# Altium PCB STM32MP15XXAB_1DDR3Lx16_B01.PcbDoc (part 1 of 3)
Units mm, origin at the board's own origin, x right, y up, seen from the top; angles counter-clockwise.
Board outline 86 x 120 mm, 4 copper layers (Top Layer, Signal Layer 1, Signal Layer 2, Bottom Layer), stack 1.571 mm thick; 144 components, 93 nets, 930 pads, 372 vias.
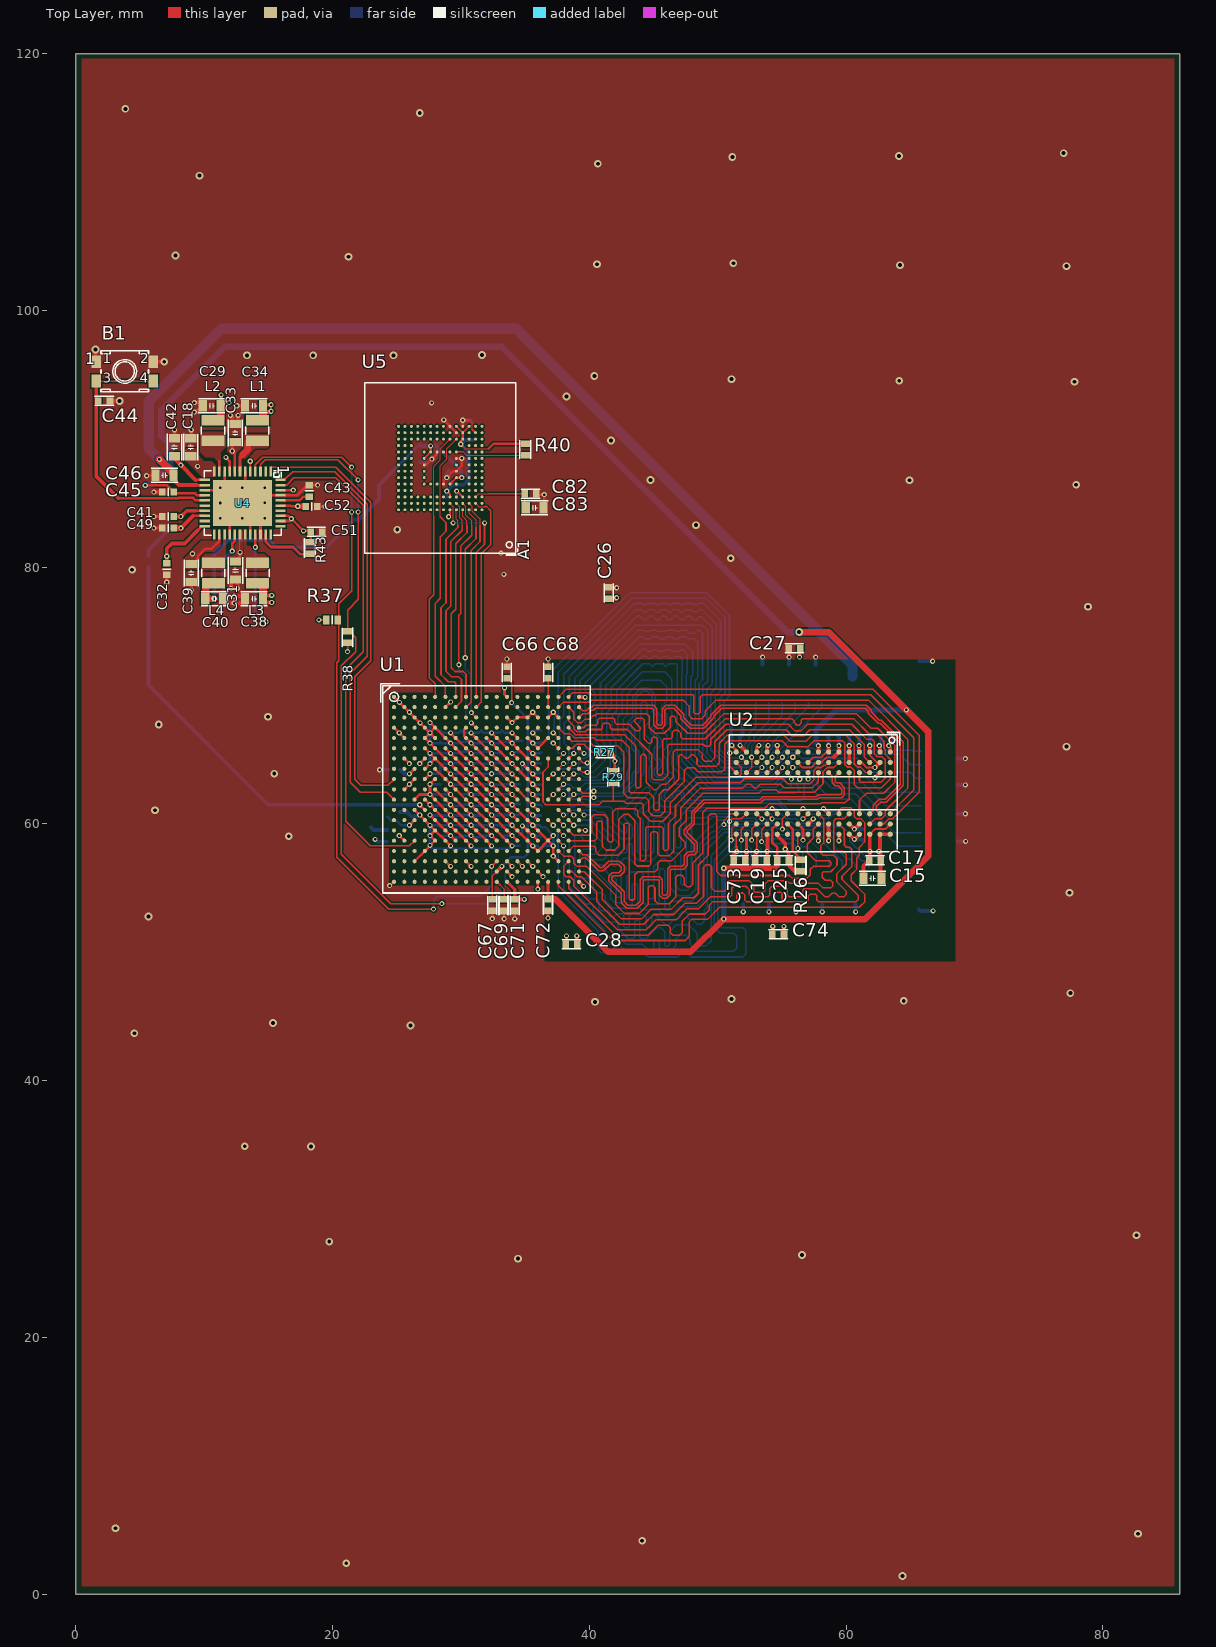
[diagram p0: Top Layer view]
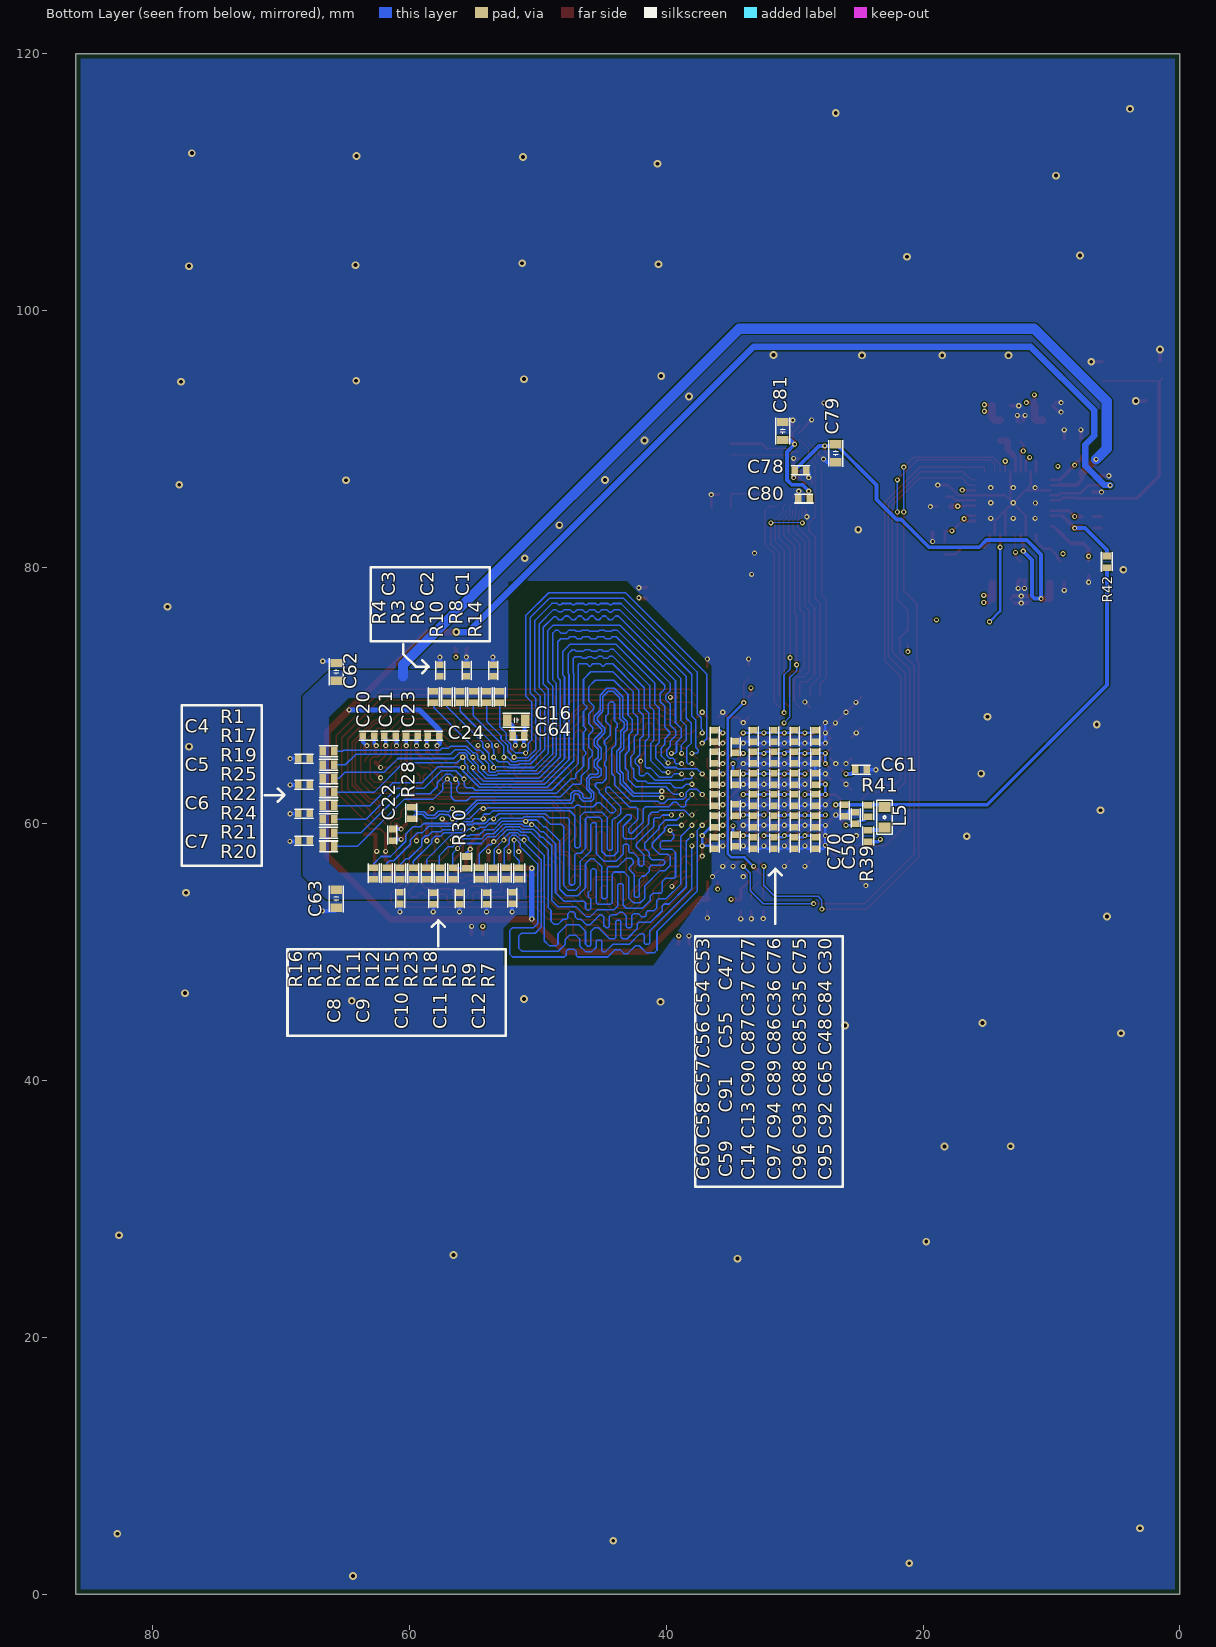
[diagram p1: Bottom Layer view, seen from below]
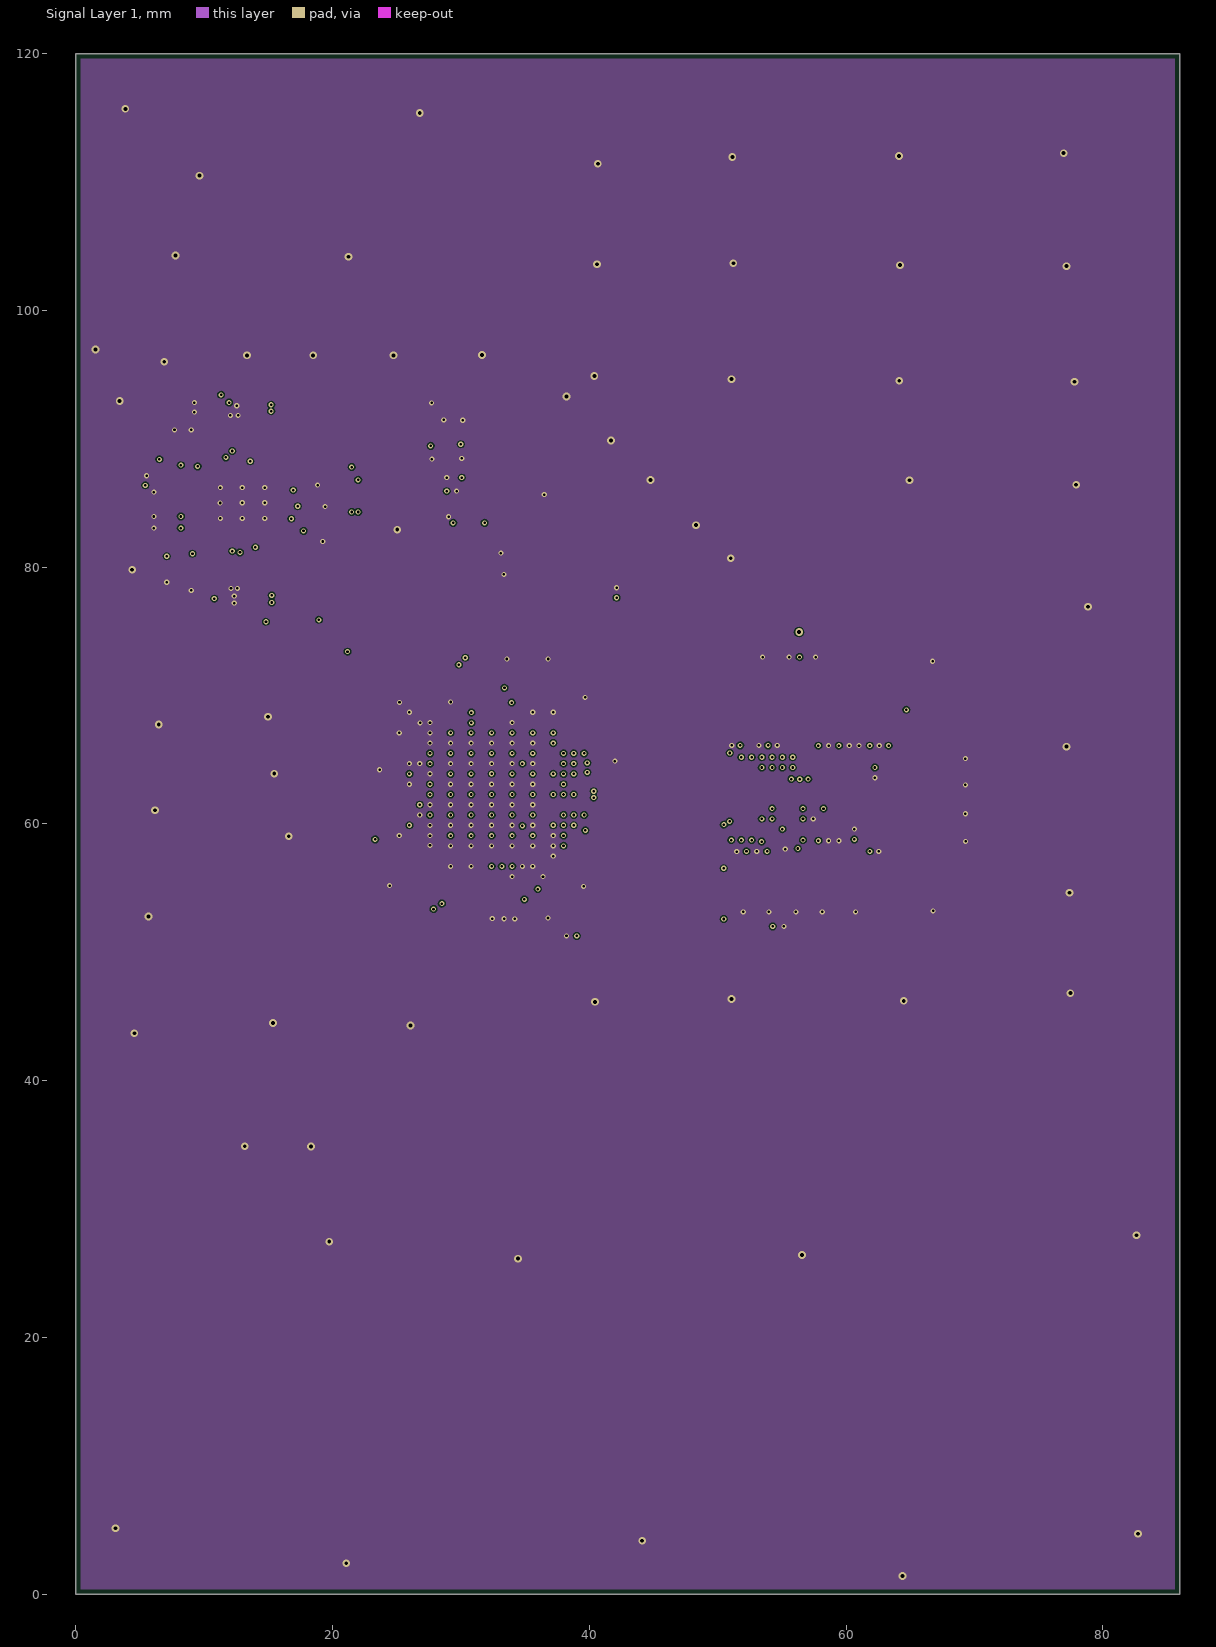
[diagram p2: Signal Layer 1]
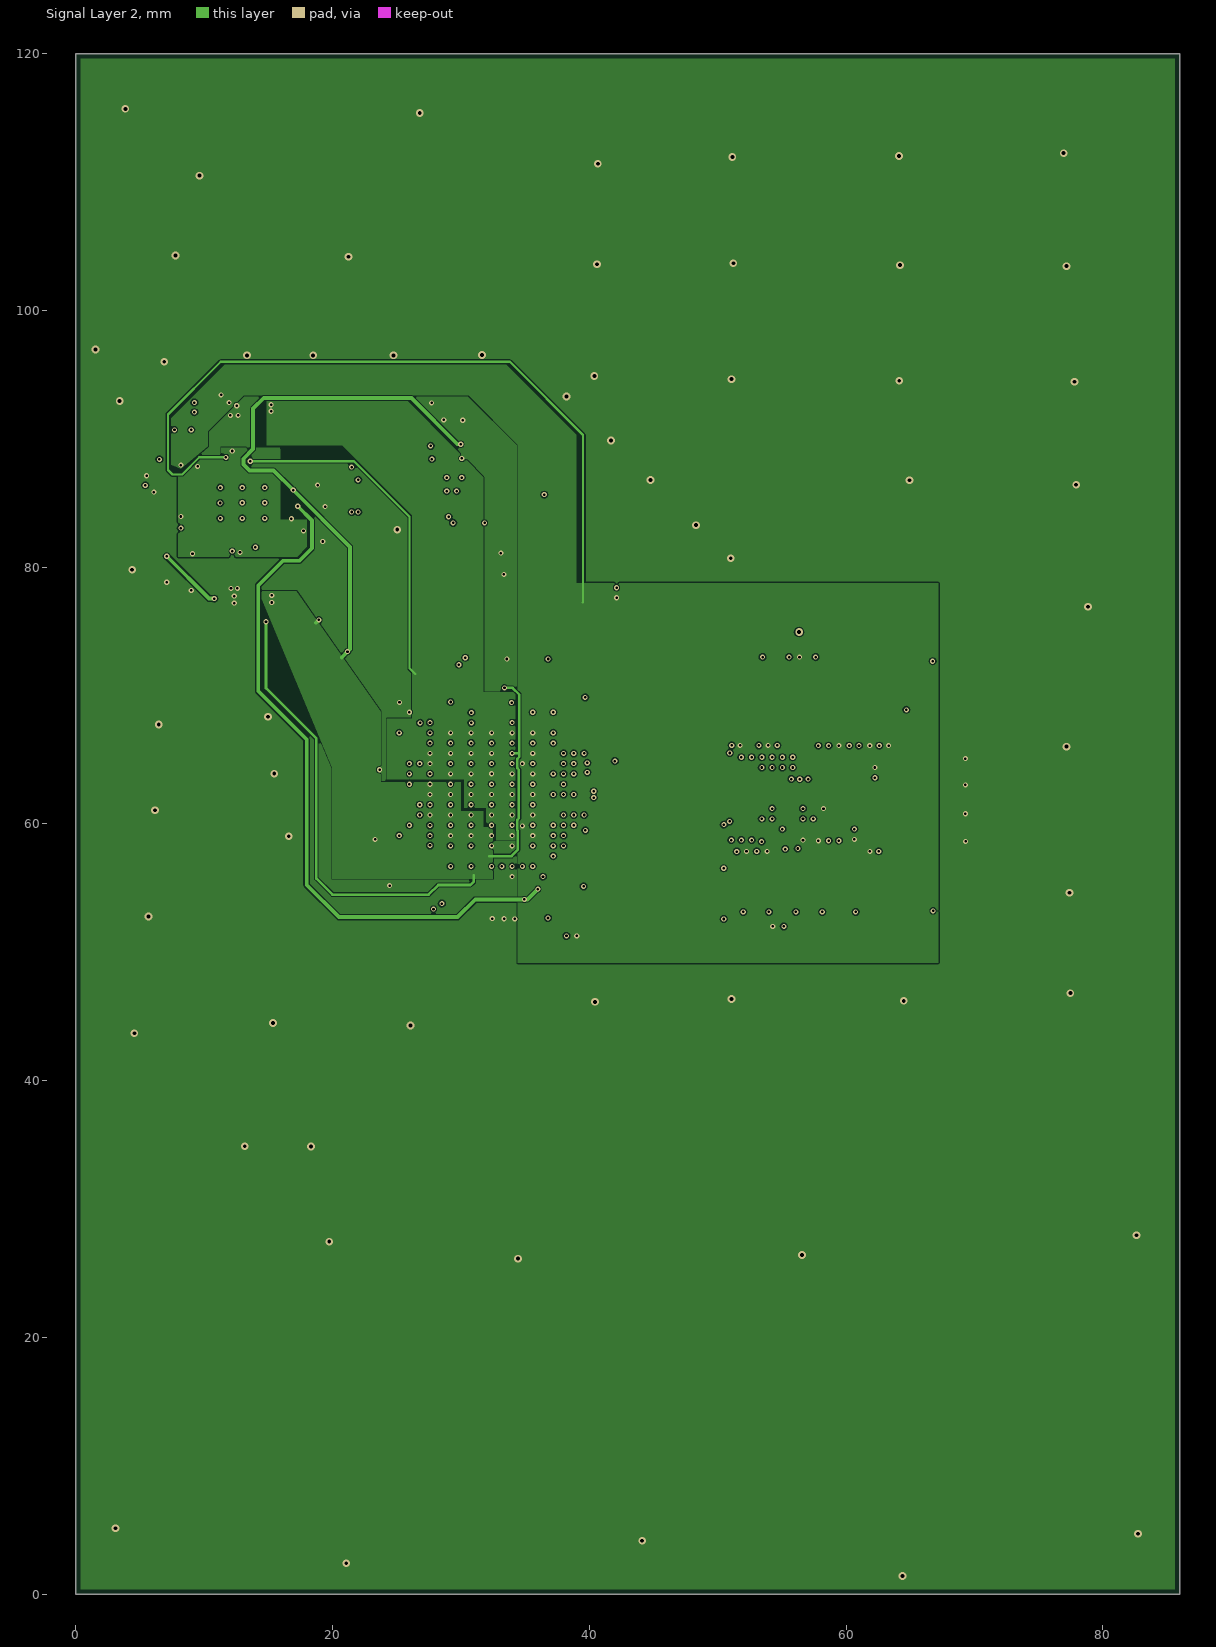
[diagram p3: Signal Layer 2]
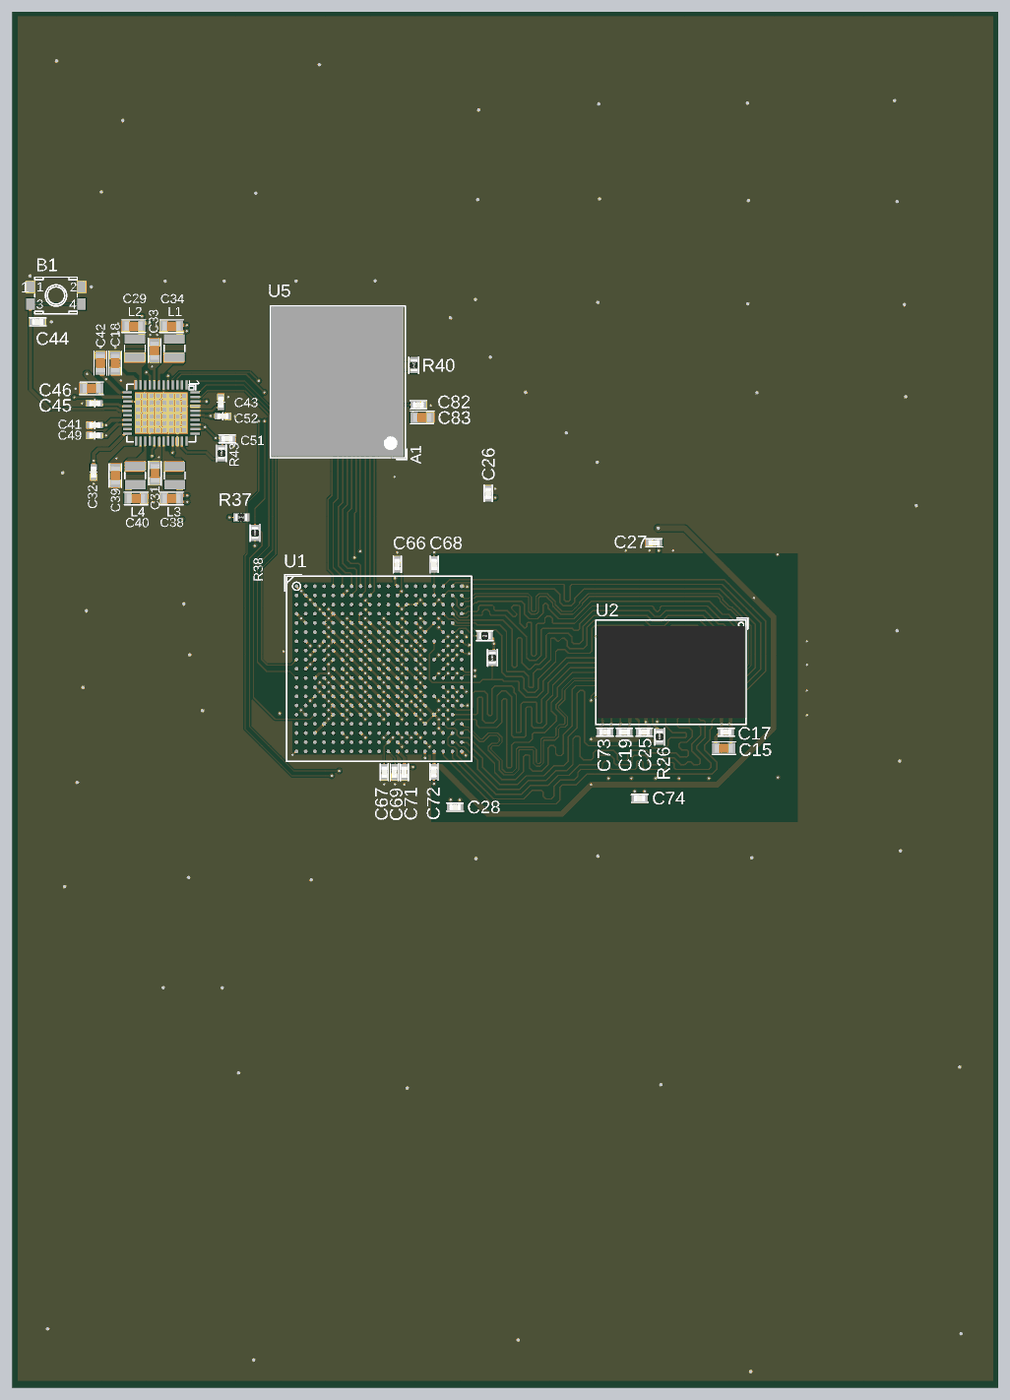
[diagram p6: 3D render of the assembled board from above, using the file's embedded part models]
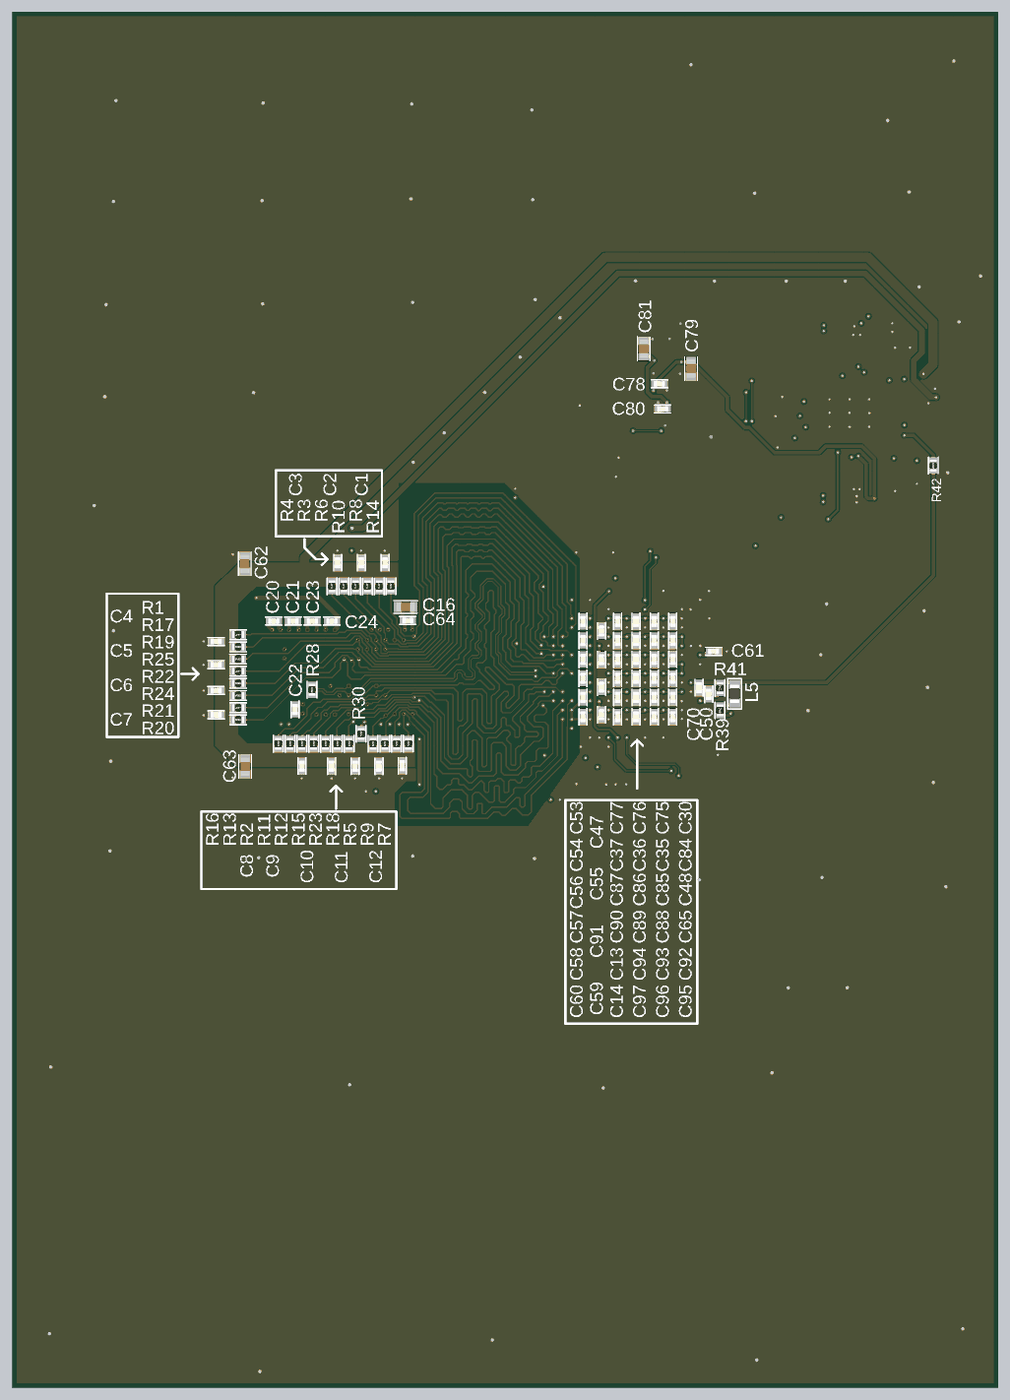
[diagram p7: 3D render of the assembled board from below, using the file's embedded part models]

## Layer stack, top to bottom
Top Solder: solder mask 0.0203, Solder Resist, Dk 3.5
Top Layer: signal copper 0.037
Dielectric 1: core 0.0986, FR-4, Dk 4.1
Signal Layer 1: signal copper 0.035
Dielectric 2: prepreg 1.23, FR-4, Dk 4.25
Signal Layer 2: signal copper 0.035
Dielectric 3: core 0.0986, FR-4, Dk 4.1
Bottom Layer: signal copper 0.037
Bottom Solder: solder mask 0.0203, Solder Resist, Dk 3.5

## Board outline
0,0 0,120 86,120 86,0

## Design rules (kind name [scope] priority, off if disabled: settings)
BoardOutlineClearance [All] p1: gap=0.4 ignorepadtopadclearanceinfootprint=FALSE
Clearance diff [InNetClass('diff')] p1: gap=0.1 ignorepadtopadclearanceinfootprint=FALSE except(0: Arc-Hole Track-Hole SMDPad-Hole THPad-Hole Via-Hole Fill-Hole Poly-Hole Region-Hole Text-Hole; 0.08: Track-SMDPad; 0.13: Track-Track; 0.15: Arc-Fill Track-Fill SMDPad-Fill THPad-Fill Via-Fill Fill-Fill; 0.2: Arc-THPad SMDPad-SMDPad SMDPad-THPad THPad-THPad)
Clearance [InNetClass('All Nets')] p2: gap=0.1 ignorepadtopadclearanceinfootprint=FALSE except(0: Arc-Hole Track-Hole SMDPad-Hole THPad-Hole Via-Hole Fill-Hole Poly-Hole Region-Hole Text-Hole; 0.09: Track-SMDPad; 0.15: Arc-Fill Track-Fill SMDPad-Fill THPad-Fill Via-Fill Fill-Fill)
ComponentClearance [All] p1 off: gap=0.025 collisioncheckmode=3 verticalgap=2540 showdistances=TRUE
DiffPairsRouting [All] p1: maxlimit=0.13 minlimit=0.13 mostfreqgap=0.13 toplayer_minwidth=0.09 toplayer_maxwidth=0.13 toplayer_prefwidth=0.1 midlayer1_minwidth=0.09 midlayer1_maxwidth=0.13 midlayer1_prefwidth=0.1 midlayer2_minwidth=0.09 midlayer2_maxwidth=0.13 midlayer2_prefwidth=0.1 bottomlayer_minwidth=0.09 bottomlayer_maxwidth=0.13 bottomlayer_prefwidth=0.1 maxuncoupledlength=0.5
FanoutControl Fanout_BGA [IsBGA] p1: bgadir=Out bgaviamode=Closest fanoutstyle=Auto fanoutdirection=Alternating viagrid=0.025 // Fanout_BGA (Default Rule)
FanoutControl Fanout_LCC [IsLCC] p2: bgadir=Out bgaviamode=Closest fanoutstyle=Auto fanoutdirection=Alternating viagrid=0.025 // Fanout_LCC (Default Rule)
FanoutControl Fanout_SOIC [IsSOIC] p3: bgadir=Out bgaviamode=Closest fanoutstyle=Auto fanoutdirection=Alternating viagrid=0.025 // Fanout_SOIC (Default Rule)
FanoutControl Fanout_Small [(CompPinCount < 5)] p4: bgadir=Out bgaviamode=Closest fanoutstyle=Auto fanoutdirection=OutThenIn viagrid=0.025 // Fanout_Small (Default Rule)
FanoutControl Fanout_Default [All] p5: bgadir=Out bgaviamode=Closest fanoutstyle=Auto fanoutdirection=Alternating viagrid=0.025 // Fanout_Default (Default Rule)
Height [All] p1 off: minheight=0 maxheight=100 prefheight=0.5
HoleSize [All] p1: absolutevalues=TRUE maxlimit=10 minlimit=0.15 maxpercent=80.000 minpercent=20.000
HoleToHoleClearance [All] p1: gap=0.25 allowstackedmicrovias=TRUE
Length Length_SDMMC1 [InNetClass('NETC_SDMMC1')] p1: maxlimit=86 minlimit=81
MinimumSolderMaskSliver [All] p1: minsoldermaskwidth=0
PlaneClearance [All] p1: clearance=0.6
PlaneConnect [All] p1: planeconnectstyle=Direct reliefexpansion=0.508 reliefentries=4 reliefconductorwidth=0.254 reliefairgap=0.254
PolygonConnect [All] p1: connectstyle=Direct reliefconductorwidth=0.254 reliefentries=4 polygonreliefangle="90 Angle" airgapwidth=0.254
RoomDefinition U_STM32_MPU_IOs [InComponentClass('U_STM32_MPU_IOs')] p1 off: confinementstyle=ConfineIn formatcopy=TRUE lockcomponents=FALSE outline 104.55,11.05 155.35,11.05 155.35,36.45 104.55,36.45
RoomDefinition U_Power_MPU [InComponentClass('U_Power_MPU')] p2 off: confinementstyle=ConfineIn formatcopy=TRUE lockcomponents=FALSE outline 87.674,18.025 101.45,18.025 101.45,24 87.674,24
RoomDefinition U_eMMC [InComponentClass('U_eMMC')] p3 off: confinementstyle=ConfineIn formatcopy=TRUE lockcomponents=FALSE outline 87.122,1.416 129.449,1.416 129.449,15.666 87.122,15.666
RoomDefinition U_1DDR3L_16bits [InComponentClass('U_1DDR3L_16bits')] p4 off: confinementstyle=ConfineIn formatcopy=TRUE lockcomponents=FALSE outline 92.5,18.4 143.3,18.4 143.3,43.8 92.5,43.8
RoomDefinition U_Power_PMIC [InComponentClass('U_Power_PMIC')] p5 off: confinementstyle=ConfineIn formatcopy=TRUE lockcomponents=FALSE outline 87.122,8.666 203.578,8.666 203.578,17.666 87.122,17.666
RoutingVias RoutingVias_GND [InNetClass('GND')] p1: holewidth=0.3 width=0.6 viastyle="Through Hole" minholewidth=0.2 minwidth=0.4 maxholewidth=0.3 maxwidth=0.6
RoutingVias RoutingVias_ALIMS [InNetClass('ALIMS')] p2: holewidth=0.3 width=0.6 viastyle="Through Hole" minholewidth=0.2 minwidth=0.4 maxholewidth=0.3 maxwidth=0.6
RoutingVias [All] p3: holewidth=0.2 width=0.4 viastyle="Through Hole" minholewidth=0.2 minwidth=0.4 maxholewidth=0.3 maxwidth=0.6
SilkToSilkClearance [All] p1: silktosilkclearance=0
SilkToSolderMaskClearance [IsPad] p1: minsilkscreentomaskgap=0 clearancetoexposedcopper=TRUE
SolderMaskExpansion [All] p1: expansion=0.05 istentingtop=FALSE
Width VDD_DDR [InNet('VDD_DDR')] p1: maxlimit=0.3 minlimit=0.1 preferedwidth=0.175
Width Width_VCORE [InNet('VDD_CORE')] p2: maxlimit=0.2 minlimit=0.175 preferedwidth=0.175
Width Width_gnd [InNet('GND')] p3: maxlimit=0.3 minlimit=0.1 preferedwidth=0.175
Width [All] p4: maxlimit=0.5 minlimit=0.09 preferedwidth=0.12 minimp=50.000000 maximp=50.000000 favimp=50.000000
15 further rules are at their usual default settings.

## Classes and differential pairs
from-to class ddr_addr_ctrl: "DDR_A0 (U1-H18 : U2-N3)" "DDR_A1 (U2-P7 : U1-M17)" "DDR_A2 (U1-G18 : U2-P3)" "DDR_A3 (U1-F19 : U2-N2)" "DDR_A4 (U2-P8 : U1-P17)" "DDR_A5 (U1-H17 : U2-P2)" "DDR_A6 (U1-N16 : U2-R8)" "DDR_A7 (U2-R2 : U1-E17)" "DDR_A8 (U1-R17 : U2-T8)" "DDR_A9 (U2-R3 : U1-G17)" "DDR_A10 (U1-M19 : U2-L7)" "DDR_A11 (U2-R7 : U1-M18)" "DDR_A12 (U1-L17 : U2-N7)" "DDR_A13 (U1-F17 : U2-T3)" "DDR_A14 (U2-T7 : U1-N18)" "DDR_A15 (U2-M7 : U1-L16)" "DDR_BA0 (U2-M2 : U1-G19)" "DDR_BA1 (U1-N17 : U2-N8)" "DDR_BA2 (U2-M3 : U1-J16)" "DDR_CASN (U1-K17 : U2-K3)" "DDR_CKE (U2-K9 : U1-P19)" "DDR_CLK_N (U2-K7 : U1-K19)" "DDR_CLK_P (U2-J7 : U1-L19)" "DDR_CSN (U1-J18 : U2-L2)" "DDR_ODT (U1-H19 : U2-K1)" "DDR_RASN (U1-L18 : U2-J3)" "DDR_WEN (U1-J17 : U2-L3)"
from-to class DDR_DQ: "DDR_DQ0 (U2-B8 : U1-A17)" "DDR_DQ1 (U2-A7 : U1-A18)" "DDR_DQ2 (U1-D18 : U2-C2)" "DDR_DQ3 (U1-B17 : U2-C8)" "DDR_DQ4 (U2-A3 : U1-E18)" "DDR_DQ5 (U1-D17 : U2-C3)" "DDR_DQ6 (U2-A2 : U1-D19)" "DDR_DQ7 (U1-B18 : U2-D7)" "DDR_DQ8 (U1-P18 : U2-G2)" "DDR_DQ9 (U2-E3 : U1-T17)" "DDR_DQ10 (U1-R18 : U2-H3)" "DDR_DQ11 (U2-H8 : U1-V19)" "DDR_DQ12 (U1-W18 : U2-F8)" "DDR_DQ13 (U2-F2 : U1-T18)" "DDR_DQ14 (U1-V18 : U2-H7)" "DDR_DQ15 (U2-F7 : U1-W17)" "DDR_DQM0 (U1-C18 : U2-D3)" "DDR_DQM1 (U2-E7 : U1-U18)" "DDR_DQS0_N (U1-B19 : U2-B7)" "DDR_DQS0_P (U2-C7 : U1-C19)" "DDR_DQS1_N (U1-T19 : U2-G3)" "DDR_DQS1_P (U2-F3 : U1-U19)"
differential pair class DIFF_CLK: DDR_CLK
differential pair class DIFF_DQS1: DDR_DQS1
differential pair class DIFF_DQS0: DDR_DQS0
polygon class POLY_DIRECT_ALL: NETC906_2_L01_P192
component class U_1DDR3L_16bits: C1 C2 C3 C4 C5 C6 C7 C8 C9 C10 C11 C12 C15 C16 C17 C19 C20 C21 C22 C23 C24 C25 C26 C27 C28 C62 C63 C64 C73 C74 R1 R2 R3 R4 R5 R6 R7 R8 R9 R10 R11 R12 R13 R14 R15 R16 R17 R18 R19 R20 R21 R22 R23 R24 R25 R26 R28 R29 R30 U2
component class U_Power_MPU: C13 C14 C30 C35 C36 C37 C47 C48 C50 C53 C54 C55 C56 C57 C58 C59 C60 C61 C65 C66 C67 C68 C69 C70 C71 C75 C76 C77 C84 C85 C86 C87 C88 C89 C90 C91 C92 C93 C94 C95 C96 C97 L5 R39 R41 R42
component class U_Power_PMIC: B1 C18 C29 C31 C32 C33 C34 C38 C39 C40 C41 C42 C43 C44 C45 C46 C49 C51 C52 L1 L2 L3 L4 R43 U4
component class U_eMMC: C78 C79 C80 C81 C82 C83 R40 U5
component class U_STM32_MPU_IOs: C72 R27 R37 R38 U1
net class eMMC_SDIO2_D[0..7]: eMMC_SDIO2_D0 eMMC_SDIO2_D1 eMMC_SDIO2_D2 eMMC_SDIO2_D3 eMMC_SDIO2_D4 eMMC_SDIO2_D5 eMMC_SDIO2_D6 eMMC_SDIO2_D7
differential pair DDR_DQS0: +DDR_DQS0_P -DDR_DQS0_N
differential pair DDR_DQS1: +DDR_DQS1_P -DDR_DQS1_N

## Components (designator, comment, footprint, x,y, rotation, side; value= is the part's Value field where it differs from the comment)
B1 "" SWI_JIUBABA_C-TS-02H-2-5-B-V-T_R_BLUE 3.825,95.25 r0 top value=SW-PUSH-TS-02H-Blue
C1 "" C0402#1 53.48,71.95 r270 bottom value=100nF
C2 "" C0402#1 55.55,71.95 r270 bottom value=100nF
C3 "" C0402#1 57.61,71.95 r270 bottom value=100nF
C4 "" C0402#1 68.21,65.08 r180 bottom value=100nF
C5 "" C0402#1 68.21,63.06 r180 bottom value=100nF
C6 "" C0402#1 68.21,60.81 r180 bottom value=100nF
C7 "" C0402#1 68.21,58.69 r180 bottom value=100nF
C8 "" C0402#1 60.73,54.22 r90 bottom value=100nF
C9 "" C0402#1 58.14,54.21 r90 bottom value=100nF
C10 "" C0402#1 56.09,54.21 r90 bottom value=100nF
C11 "" C0402#1 54.01,54.21 r90 bottom value=100nF
C12 "" C0402#1 51.99,54.25 r90 bottom value=100nF
C13 "" C0402#1 33.2,60.21 r90 bottom value=1uF
C14 "" C0402#1 33.2,58.52 r90 bottom value=1uF
C15 "" C0603#1 62.06,55.78 r180 top value=10uF
C16 "" C0603#1 51.69,68.09 r0 bottom value=10uF
C17 "" C0402#1 62.25,57.17 r180 top value=100nF
C18 "" C0603#2 8.975,89.35 r270 bottom value=10uF
C19 "" C0402#1 53.39,57.17 r0 top value=100nF
C20 "" C0402#1 63.19,66.86 r0 bottom value=100nF
C21 "" C0402#1 61.51,66.86 r0 bottom value=100nF
C22 "" C0402#1 61.33,59.16 r90 bottom value=100nF
C23 "" C0402#1 59.82,66.86 r180 bottom value=100nF
C24 "" C0402#1 58.12,66.86 r180 bottom value=100nF
C25 "" C0402#1 55.11,57.17 r180 top value=100nF
C26 "" C0402#1 41.52,78 r270 top value=100nF
C27 "" C0402#1 55.98,73.68 r0 top value=100nF
C28 "" C0402#1 38.63,50.63 r0 top value=100nF
C29 "" C0603#2 10.6,92.575 r0 bottom value=22uF
C30 "" C0402#1 28.4,66.84 r90 bottom value=1uF
C31 "" C0603#2 12.45,79.75 r90 bottom value=10uF
C32 "" C0402#2 7.1,79.85 r90 bottom value=1uF
C33 "" C0603#2 12.425,90.45 r270 bottom value=10uF
C34 "" C0603#2 13.9,92.575 r0 bottom value=22uF
C35 "" C0402#1 30,65.17 r90 bottom value=1uF
C36 "" C0402#1 31.6,65.17 r90 bottom value=1uF
C37 "" C0402#1 33.2,65.17 r90 bottom value=1uF
C38 "" C0603#2 13.9,77.55 r0 bottom value=22uF
C39 "" C0603#2 9,79.55 r90 bottom value=10uF
C40 "" C0603#2 10.8,77.55 r180 bottom value=22uF
C41 "" C0402#2 7.2,83.95 r0 bottom value=1uF
C42 "" C0603#2 7.7,89.35 r270 bottom value=10uF
C43 "" C0402#2 18.2,85.95 r270 bottom value=4.7uF
C44 "" C0402#1 2.225,92.95 r180 top value=10nF
C45 "" C0402#1 7.2,85.85 r0 top value=1uF
C46 "" C0603#1 6.925,87.15 r0 top value=10uF
C47 "" C0402#1 34.6,66 r270 bottom value=1uF
C48 "" C0402#1 28.4,63.52 r270 bottom value=1uF
C49 "" C0402#2 7.2,83.05 r0 bottom value=4.7uF
C50 "" C0402#1 25.25,60.475 r270 bottom value=1uF
C51 "" C0402#1 18.75,82.75 r0 top value=4.7uF
C52 "" C0402#1 18.375,84.725 r180 top value=4.7uF
C53 "" C0402#1 36.22,66.84 r90 bottom value=1uF
C54 "" C0402#1 36.22,65.17 r90 bottom value=1nF
C55 "" C0402#1 34.6,63.5 r90 bottom value=1uF
C56 "" C0402#1 36.22,63.52 r90 bottom value=1uF
C57 "" C0402#1 36.22,61.87 r90 bottom value=1nF
C58 "" C0402#1 36.22,60.21 r90 bottom value=1uF
C59 "" C0402#1 34.6,58.7 r90 bottom value=1uF
C60 "" C0402#1 36.22,58.52 r90 bottom value=1uF
C61 "" C0402#1 24.825,64.225 r0 bottom value=100nF
C62 "" C0603#1 65.71,71.85 r270 bottom value=22uF
C63 "" C0603#1 65.69,54.18 r90 bottom value=22uF
C64 "" C0402#1 51.5,66.91 r0 bottom value=100nF
C65 "" C0402#1 28.4,61.87 r90 bottom value=1uF
C66 "" C0402#1 33.59,71.8 r270 top value=100nF
C67 "Capacitor" C0402#1 32.45,53.69 r90 top value=2.2uF
C68 "Capacitor" C0402#1 36.8,71.8 r270 top value=2.2uF
C69 "Capacitor" C0402#1 33.325,53.675 r90 top value=2.2uF
C70 "" C0402#1 26.1,61.05 r90 bottom value=1uF
C71 "" C0402#1 34.2,53.675 r90 top value=100nF
C72 "" C0402#1 36.79,53.71 r90 top value=100nF
C73 "" C0402#1 51.7,57.17 r0 top value=100nF
C74 "" C0402#1 54.72,51.4 r180 top value=100nF
C75 "" C0402#1 30,66.84 r90 bottom value=1uF
C76 "" C0402#1 31.6,66.84 r90 bottom value=1uF
C77 "" C0402#1 33.2,66.84 r90 bottom value=1uF
C78 "" C0402#1 29.55,87.55 r0 bottom value=100nF
C79 "" C0603#1 26.8,88.875 r90 bottom value=2.2uF
C80 "" C0402#1 29.275,85.35 r180 bottom value=100nF
C81 "" C0603#1 30.925,90.6 r270 bottom value=2.2uF
C82 "" C0402#1 35.425,85.725 r180 top value=100nF
C83 "" C0603#1 35.75,84.625 r180 top value=2.2uF
C84 "" C0402#1 28.4,65.17 r90 bottom value=1uF
C85 "" C0402#1 30,63.52 r90 bottom value=1uF
C86 "" C0402#1 31.6,63.52 r90 bottom value=1uF
C87 "" C0402#1 33.2,63.52 r90 bottom value=1uF
C88 "" C0402#1 30,61.87 r90 bottom value=1uF
C89 "" C0402#1 31.6,61.87 r90 bottom value=1uF
C90 "" C0402#1 33.2,61.87 r90 bottom value=1uF
C91 "" C0402#1 34.6,61.1 r270 bottom value=1uF
C92 "" C0402#1 28.4,60.21 r90 bottom value=1uF
C93 "" C0402#1 30,60.21 r90 bottom value=1uF
C94 "" C0402#1 31.6,60.21 r90 bottom value=1uF
C95 "" C0402#1 28.4,58.52 r90 bottom value=1uF
C96 "" C0402#1 30,58.52 r90 bottom value=1uF
C97 "" C0402#1 31.6,58.52 r90 bottom value=1uF
L1 "" IND_MURATA_DFE201612P 14.15,90.65 r90 bottom value=DFE201612P-1R0M
L2 "" IND_MURATA_DFE201612P 10.7,90.65 r90 bottom value=DFE201612P-1R0M
L3 "" IND_MURATA_DFE201612P 14.175,79.55 r270 bottom value=DFE201612P-1R0M
L4 "" IND_MURATA_DFE201612P 10.725,79.55 r270 bottom value=DFE201612P-1R0M
L5 "" L0603_H0P8 23,60.525 r90 bottom value=LQM18FN4R7M00D
R1 "" R0402#1 66.3,65.67 r0 bottom value=56R
R2 "" R0402#1 60.73,56.16 r270 bottom value=56R
R3 "" R0402#1 57.08,69.9 r90 bottom value=56R
R4 "" R0402#1 58.11,69.9 r90 bottom value=56R
R5 "" R0402#1 53.5,56.16 r270 bottom value=56R
R6 "" R0402#1 56.05,69.9 r90 bottom value=56R
R7 "" R0402#1 51.45,56.16 r270 bottom value=56R
R8 "" R0402#1 53.99,69.9 r90 bottom value=56R
R9 "" R0402#1 52.48,56.16 r270 bottom value=56R
R10 "" R0402#1 55.02,69.9 r90 bottom value=56R
R11 "" R0402#1 59.7,56.16 r270 bottom value=56R
R12 "" R0402#1 58.67,56.16 r270 bottom value=56R
R13 "" R0402#1 61.76,56.16 r270 bottom value=56R
R14 "" R0402#1 52.97,69.9 r90 bottom value=56R
R15 "" R0402#1 57.64,56.16 r270 bottom value=56R
R16 "" R0402#1 62.79,56.16 r270 bottom value=56R
R17 "" R0402#1 66.3,64.61 r0 bottom value=56R
R18 "" R0402#1 54.53,56.16 r270 bottom value=56R
R19 "" R0402#1 66.3,63.55 r0 bottom value=56R
R20 "" R0402#1 66.3,58.25 r0 bottom value=56R
R21 "" R0402#1 66.3,59.31 r0 bottom value=56R
R22 "" R0402#1 66.3,61.43 r0 bottom value=56R
R23 "" R0402#1 56.61,56.16 r270 bottom value=56R
R24 "" R0402#1 66.3,60.37 r0 bottom value=56R
R25 "" R0402#1 66.3,62.49 r0 bottom value=56R
R26 "" R0402#1 56.46,56.78 r90 top value=240R
R27 "" R0402#1 41.22,65.58 r0 top value=240R
R28 "" R0402#1 59.85,60.87 r270 bottom value=100R
R29 "" R0402#1 41.875,63.65 r270 top value=10K
R30 "" R0402#1 55.57,57.02 r270 bottom value=10K
R37 "" R0402#1 19.975,75.9 r0 top value=1K5
R38 "" R0402#1 21.175,74.55 r90 top value=1K5
R39 "" R0402#1 24.275,59.075 r90 bottom value=0R
R40 "" R0402#1 35.025,89.175 r90 top value=10K
R41 "" R0402#1 24.275,61.025 r270 bottom value=0R
R42 "" R0402#1 5.675,80.425 r270 bottom value=0R
R43 "" R0402#2 18.25,81.5 r90 bottom value=47K
U1 "STM32MP157CAB3" ICC_LFBGA354_16X16_STM32MP157CAB3_P080 32,62.7 r0 top locked
U2 "" ICC_VFBGA96_9x13_P080 57.45,62.4 r270 top locked value=NT5CC256M16ER-EK
U4 "" ICC_WFQFN44-EPAD_5X6_P040 13,85 r270 top value=STPMIC1APQR
U5 "" ICC_P-WFBGA153_13X11P5_P050 28.4,87.725 r90 top locked value=THGBMDG5D1LBAIL

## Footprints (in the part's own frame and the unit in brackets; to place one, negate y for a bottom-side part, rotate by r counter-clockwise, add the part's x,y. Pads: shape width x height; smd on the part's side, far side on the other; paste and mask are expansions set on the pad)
C0402#1 [mm]
  rect 0.51x0.56 smd mask+0.05: 1(-0.45,0) 2(0.45,0)
  silkscreen extent -0.72,-0.35 0.72,0.35, body extent -0.5,-0.3 0.5,0.3, height 0.4
C0402#2 [mm]
  rect 0.51x0.56 smd far side mask+0.05: 1(-0.45,0) 2(0.45,0)
  body extent -0.5,-0.3 0.5,0.3, height 0.4
C0603#1 [mm]
  rect 0.64x0.89 smd mask+0.05: 1(-0.7,0) 2(0.7,0)
  silkscreen extent -1.05,-0.55 1.02,0.55, body extent -0.9,-0.5 0.9,0.5, height 1.4
C0603#2 [mm]
  rect 0.64x0.89 smd far side mask+0.05: 1(-0.7,0) 2(0.7,0)
  body extent -0.9,-0.5 0.9,0.5, height 1.4
ICC_LFBGA354_16X16_STM32MP157CAB3_P080 [mm] "MCD-01805"
  round 0.32 smd paste+0 mask+0.05: A1(-7.2,7.2) A2(-6.4,7.2) A3(-5.6,7.2) A4(-4.8,7.2) A5(-4,7.2) A6(-3.2,7.2) A7(-2.4,7.2) A8(-1.6,7.2) A9(-0.8,7.2) A10(0,7.2) A11(0.8,7.2) A12(1.6,7.2) A13(2.4,7.2) A14(3.2,7.2) A15(4,7.2) A16(4.8,7.2) A17(5.6,7.2) A18(6.4,7.2) A19(7.2,7.2) B1(-7.2,6.4) B2(-6.4,6.4) B3(-5.6,6.4) B4(-4.8,6.4) B5(-4,6.4) B6(-3.2,6.4) B7(-2.4,6.4) B8(-1.6,6.4) B9(-0.8,6.4) B10(0,6.4) B11(0.8,6.4) B12(1.6,6.4) B13(2.4,6.4) B14(3.2,6.4) B15(4,6.4) B16(4.8,6.4) B17(5.6,6.4) B18(6.4,6.4) B19(7.2,6.4) C1(-7.2,5.6) C2(-6.4,5.6) C3(-5.6,5.6) C4(-4.8,5.6) C5(-4,5.6) C6(-3.2,5.6) C7(-2.4,5.6) C8(-1.6,5.6) C9(-0.8,5.6) C10(0,5.6) C11(0.8,5.6) C12(1.6,5.6) C13(2.4,5.6) C14(3.2,5.6) C15(4,5.6) C16(4.8,5.6) C17(5.6,5.6) C18(6.4,5.6) C19(7.2,5.6) D1(-7.2,4.8) D2(-6.4,4.8) D3(-5.6,4.8) D4(-4.8,4.8) D5(-4,4.8) D6(-3.2,4.8) D7(-2.4,4.8) D8(-1.6,4.8) D9(-0.8,4.8) D10(0,4.8) D11(0.8,4.8) D12(1.6,4.8) D13(2.4,4.8) D14(3.2,4.8) D15(4,4.8) D16(4.8,4.8) D17(5.6,4.8) D18(6.4,4.8) D19(7.2,4.8) E1(-7.2,4) E2(-6.4,4) E3(-5.6,4) E4(-4.8,4) E5(-4,4) E6(-3.2,4) E7(-2.4,4) E8(-1.6,4) E9(-0.8,4) E10(0,4) E11(0.8,4) E12(1.6,4) E13(2.4,4) E14(3.2,4) E15(4,4) E16(4.8,4) E17(5.6,4) E18(6.4,4) F1(-7.2,3.2) F2(-6.4,3.2) F3(-5.6,3.2) F4(-4.8,3.2) F5(-4,3.2) F6(-3.2,3.2) F7(-2.4,3.2) F8(-1.6,3.2) F9(-0.8,3.2) F10(0,3.2) F11(0.8,3.2) F12(1.6,3.2) F13(2.4,3.2) F14(3.2,3.2) F15(4,3.2) F17(5.6,3.2) F18(6.4,3.2) F19(7.2,3.2) G1(-7.2,2.4) G2(-6.4,2.4) G3(-5.6,2.4) G4(-4.8,2.4) G5(-4,2.4) G6(-3.2,2.4) G7(-2.4,2.4) G8(-1.6,2.4) G9(-0.8,2.4) G10(0,2.4) G11(0.8,2.4) G12(1.6,2.4) G13(2.4,2.4) G14(3.2,2.4) G15(4,2.4) G16(4.8,2.4) G17(5.6,2.4) G18(6.4,2.4) G19(7.2,2.4) H1(-7.2,1.6) H2(-6.4,1.6) H3(-5.6,1.6) H4(-4.8,1.6) H5(-4,1.6) H6(-3.2,1.6) H7(-2.4,1.6) H8(-1.6,1.6) H9(-0.8,1.6) H10(0,1.6) H11(0.8,1.6) H12(1.6,1.6) H13(2.4,1.6) H14(3.2,1.6) H15(4,1.6) H17(5.6,1.6) H18(6.4,1.6) H19(7.2,1.6) J1(-7.2,0.8) J2(-6.4,0.8) J3(-5.6,0.8) J4(-4.8,0.8) J5(-4,0.8) J6(-3.2,0.8) J7(-2.4,0.8) J8(-1.6,0.8) J9(-0.8,0.8) J10(0,0.8) J11(0.8,0.8) J12(1.6,0.8) J13(2.4,0.8) J14(3.2,0.8) J15(4,0.8) J16(4.8,0.8) J17(5.6,0.8) J18(6.4,0.8) J19(7.2,0.8) K1(-7.2,0) K2(-6.4,0) K3(-5.6,0) K4(-4.8,0) K5(-4,0) K6(-3.2,0) K7(-2.4,0) K8(-1.6,0) K9(-0.8,0) K10(0,0) K11(0.8,0) K12(1.6,0) K13(2.4,0) K14(3.2,0) K15(4,0) K17(5.6,0) K18(6.4,0) K19(7.2,0) L1(-7.2,-0.8) L2(-6.4,-0.8) L3(-5.6,-0.8) L4(-4.8,-0.8) L5(-4,-0.8) L6(-3.2,-0.8) L7(-2.4,-0.8) L8(-1.6,-0.8) L9(-0.8,-0.8) L10(0,-0.8) L11(0.8,-0.8) L12(1.6,-0.8) L13(2.4,-0.8) L14(3.2,-0.8) L15(4,-0.8) L16(4.8,-0.8) L17(5.6,-0.8) L18(6.4,-0.8) L19(7.2,-0.8) M1(-7.2,-1.6) M2(-6.4,-1.6) M3(-5.6,-1.6) M4(-4.8,-1.6) M5(-4,-1.6) M6(-3.2,-1.6) M7(-2.4,-1.6) M8(-1.6,-1.6) M9(-0.8,-1.6) M10(0,-1.6) M11(0.8,-1.6) M12(1.6,-1.6) M13(2.4,-1.6) M14(3.2,-1.6) M15(4,-1.6) M17(5.6,-1.6) M18(6.4,-1.6) M19(7.2,-1.6) N1(-7.2,-2.4) N2(-6.4,-2.4) N3(-5.6,-2.4) N4(-4.8,-2.4) N5(-4,-2.4) N6(-3.2,-2.4) N7(-2.4,-2.4) N8(-1.6,-2.4) N9(-0.8,-2.4) N10(0,-2.4) N11(0.8,-2.4) N12(1.6,-2.4) N13(2.4,-2.4) N14(3.2,-2.4) N15(4,-2.4) N16(4.8,-2.4) N17(5.6,-2.4) N18(6.4,-2.4) N19(7.2,-2.4) P1(-7.2,-3.2) P2(-6.4,-3.2) P3(-5.6,-3.2) P4(-4.8,-3.2) P5(-4,-3.2) P6(-3.2,-3.2) P7(-2.4,-3.2) P8(-1.6,-3.2) P9(-0.8,-3.2) P10(0,-3.2) P11(0.8,-3.2) P12(1.6,-3.2) P13(2.4,-3.2) P14(3.2,-3.2) P15(4,-3.2) P17(5.6,-3.2) P18(6.4,-3.2) P19(7.2,-3.2) R1(-7.2,-4) R2(-6.4,-4) R3(-5.6,-4) R4(-4.8,-4) R5(-4,-4) R6(-3.2,-4) R7(-2.4,-4) R8(-1.6,-4) R9(-0.8,-4) R10(0,-4) R11(0.8,-4) R12(1.6,-4) R13(2.4,-4) R14(3.2,-4) R15(4,-4) R16(4.8,-4) R17(5.6,-4) R18(6.4,-4) T1(-7.2,-4.8) T2(-6.4,-4.8) T3(-5.6,-4.8) T4(-4.8,-4.8) T5(-4,-4.8) T6(-3.2,-4.8) T7(-2.4,-4.8) T8(-1.6,-4.8) T9(-0.8,-4.8) T10(0,-4.8) T11(0.8,-4.8) T12(1.6,-4.8) T13(2.4,-4.8) T14(3.2,-4.8) T15(4,-4.8) T16(4.8,-4.8) T17(5.6,-4.8) T18(6.4,-4.8) T19(7.2,-4.8) U1(-7.2,-5.6) U2(-6.4,-5.6) U3(-5.6,-5.6) U4(-4.8,-5.6) U5(-4,-5.6) U6(-3.2,-5.6) U7(-2.4,-5.6) U8(-1.6,-5.6) U9(-0.8,-5.6) U10(0,-5.6) U11(0.8,-5.6) U12(1.6,-5.6) U13(2.4,-5.6) U14(3.2,-5.6) U15(4,-5.6) U16(4.8,-5.6) U17(5.6,-5.6) U18(6.4,-5.6) U19(7.2,-5.6) V1(-7.2,-6.4) V2(-6.4,-6.4) V3(-5.6,-6.4) V4(-4.8,-6.4) V5(-4,-6.4) V6(-3.2,-6.4) V7(-2.4,-6.4) V8(-1.6,-6.4) V9(-0.8,-6.4) V10(0,-6.4) V11(0.8,-6.4) V12(1.6,-6.4) V13(2.4,-6.4) V14(3.2,-6.4) V15(4,-6.4) V16(4.8,-6.4) V17(5.6,-6.4) V18(6.4,-6.4) V19(7.2,-6.4) W1(-7.2,-7.2) W2(-6.4,-7.2) W3(-5.6,-7.2) W4(-4.8,-7.2) W5(-4,-7.2) W6(-3.2,-7.2) W7(-2.4,-7.2) W8(-1.6,-7.2) W9(-0.8,-7.2) W10(0,-7.2) W11(0.8,-7.2) W12(1.6,-7.2) W13(2.4,-7.2) W14(3.2,-7.2) W15(4,-7.2) W16(4.8,-7.2) W17(5.6,-7.2) W18(6.4,-7.2) W19(7.2,-7.2)
  silkscreen extent -8.23,-8.08 8.08,8.23, body extent -8.08,-8.08 8.08,8.08, height 1.3
ICC_P-WFBGA153_13X11P5_P050 [mm]
  round 0.23 smd mask+0.05: A1(-3.25,-3.25) A2(-3.25,-2.75) A3(-3.25,-2.25) A4(-3.25,-1.75) A5(-3.25,-1.25) A6(-3.25,-0.75) A7(-3.25,-0.25) A8(-3.25,0.25) A9(-3.25,0.75) A10(-3.25,1.25) A11(-3.25,1.75) A12(-3.25,2.25) A13(-3.25,2.75) A14(-3.25,3.25) B1(-2.75,-3.25) B2(-2.75,-2.75) B3(-2.75,-2.25) B4(-2.75,-1.75) B5(-2.75,-1.25) B6(-2.75,-0.75) B7(-2.75,-0.25) B8(-2.75,0.25) B9(-2.75,0.75) B10(-2.75,1.25) B11(-2.75,1.75) B12(-2.75,2.25) B13(-2.75,2.75) B14(-2.75,3.25) C1(-2.25,-3.25) C2(-2.25,-2.75) C3(-2.25,-2.25) C4(-2.25,-1.75) C5(-2.25,-1.25) C6(-2.25,-0.75) C7(-2.25,-0.25) C8(-2.25,0.25) C9(-2.25,0.75) C10(-2.25,1.25) C11(-2.25,1.75) C12(-2.25,2.25) C13(-2.25,2.75) C14(-2.25,3.25) D1(-1.75,-3.25) D2(-1.75,-2.75) D3(-1.75,-2.25) D4(-1.75,-1.75) D12(-1.75,2.25) D13(-1.75,2.75) D14(-1.75,3.25) E1(-1.25,-3.25) E2(-1.25,-2.75) E3(-1.25,-2.25) E5(-1.25,-1.25) E6(-1.25,-0.75) E7(-1.25,-0.25) E8(-1.25,0.25) E9(-1.25,0.75) E10(-1.25,1.25) E12(-1.25,2.25) E13(-1.25,2.75) E14(-1.25,3.25) F1(-0.75,-3.25) F2(-0.75,-2.75) F3(-0.75,-2.25) F5(-0.75,-1.25) F10(-0.75,1.25) F12(-0.75,2.25) F13(-0.75,2.75) F14(-0.75,3.25) G1(-0.25,-3.25) G2(-0.25,-2.75) G3(-0.25,-2.25) G5(-0.25,-1.25) G10(-0.25,1.25) G12(-0.25,2.25) G13(-0.25,2.75) G14(-0.25,3.25) H1(0.25,-3.25) H2(0.25,-2.75) H3(0.25,-2.25) H5(0.25,-1.25) H10(0.25,1.25) H12(0.25,2.25) H13(0.25,2.75) H14(0.25,3.25) J1(0.75,-3.25) J2(0.75,-2.75) J3(0.75,-2.25) J5(0.75,-1.25) J10(0.75,1.25) J12(0.75,2.25) J13(0.75,2.75) J14(0.75,3.25) K1(1.25,-3.25) K2(1.25,-2.75) K3(1.25,-2.25) K5(1.25,-1.25) K6(1.25,-0.75) K7(1.25,-0.25) K8(1.25,0.25) K9(1.25,0.75) K10(1.25,1.25) K12(1.25,2.25) K13(1.25,2.75) K14(1.25,3.25) L1(1.75,-3.25) L2(1.75,-2.75) L3(1.75,-2.25) L12(1.75,2.25) L13(1.75,2.75) L14(1.75,3.25) M1(2.25,-3.25) M2(2.25,-2.75) M3(2.25,-2.25) M4(2.25,-1.75) M5(2.25,-1.25) M6(2.25,-0.75) M7(2.25,-0.25) M8(2.25,0.25) M9(2.25,0.75) M10(2.25,1.25) M11(2.25,1.75) M12(2.25,2.25) M13(2.25,2.75) M14(2.25,3.25) N1(2.75,-3.25) N2(2.75,-2.75) N3(2.75,-2.25) N4(2.75,-1.75) N5(2.75,-1.25) N6(2.75,-0.75) N7(2.75,-0.25) N8(2.75,0.25) N9(2.75,0.75) N10(2.75,1.25) N11(2.75,1.75) N12(2.75,2.25) N13(2.75,2.75) N14(2.75,3.25) P1(3.25,-3.25) P2(3.25,-2.75) P3(3.25,-2.25) P4(3.25,-1.75) P5(3.25,-1.25) P6(3.25,-0.75) P7(3.25,-0.25) P8(3.25,0.25) P9(3.25,0.75) P10(3.25,1.25) P11(3.25,1.75) P12(3.25,2.25) P13(3.25,2.75) P14(3.25,3.25)
  silkscreen extent -6.78,-6.02 6.63,5.87, body extent -6.55,-5.8 6.55,5.8, height 1
ICC_VFBGA96_9x13_P080 [mm]
  round 0.4 smd mask+0.05: A1(-3.2,6) A2(-2.4,6) A3(-1.6,6) A7(1.6,6) A8(2.4,6) A9(3.2,6) B1(-3.2,5.2) B2(-2.4,5.2) B3(-1.6,5.2) B7(1.6,5.2) B8(2.4,5.2) B9(3.2,5.2) C1(-3.2,4.4) C2(-2.4,4.4) C3(-1.6,4.4) C7(1.6,4.4) C8(2.4,4.4) C9(3.2,4.4) D1(-3.2,3.6) D2(-2.4,3.6) D3(-1.6,3.6) D7(1.6,3.6) D8(2.4,3.6) D9(3.2,3.6) E1(-3.2,2.8) E2(-2.4,2.8) E3(-1.6,2.8) E7(1.6,2.8) E8(2.4,2.8) E9(3.2,2.8) F1(-3.2,2) F2(-2.4,2) F3(-1.6,2) F7(1.6,2) F8(2.4,2) F9(3.2,2) G1(-3.2,1.2) G2(-2.4,1.2) G3(-1.6,1.2) G7(1.6,1.2) G8(2.4,1.2) G9(3.2,1.2) H1(-3.2,0.4) H2(-2.4,0.4) H3(-1.6,0.4) H7(1.6,0.4) H8(2.4,0.4) H9(3.2,0.4) J1(-3.2,-0.4) J2(-2.4,-0.4) J3(-1.6,-0.4) J7(1.6,-0.4) J8(2.4,-0.4) J9(3.2,-0.4) K1(-3.2,-1.2) K2(-2.4,-1.2) K3(-1.6,-1.2) K7(1.6,-1.2) K8(2.4,-1.2) K9(3.2,-1.2) L1(-3.2,-2) L2(-2.4,-2) L3(-1.6,-2) L7(1.6,-2) L8(2.4,-2) L9(3.2,-2) M1(-3.2,-2.8) M2(-2.4,-2.8) M3(-1.6,-2.8) M7(1.6,-2.8) M8(2.4,-2.8) M9(3.2,-2.8) N1(-3.2,-3.6) N2(-2.4,-3.6) N3(-1.6,-3.6) N7(1.6,-3.6) N8(2.4,-3.6) N9(3.2,-3.6) P1(-3.2,-4.4) P2(-2.4,-4.4) P3(-1.6,-4.4) P7(1.6,-4.4) P8(2.4,-4.4) P9(3.2,-4.4) R1(-3.2,-5.2) R2(-2.4,-5.2) R3(-1.6,-5.2) R7(1.6,-5.2) R8(2.4,-5.2) R9(3.2,-5.2) T1(-3.2,-6) T2(-2.4,-6) T3(-1.6,-6) T7(1.6,-6) T8(2.4,-6) T9(3.2,-6)
  silkscreen extent -4.72,-6.55 4.55,6.73, body extent -4.55,-6.55 4.55,6.55, height 1
ICC_WFQFN44-EPAD_5X6_P040 [mm]
  rect 0.8x0.2 smd mask+0.05: 1(-2.45,2.2) 2(-2.45,1.8) 3(-2.45,1.4) 4(-2.45,1) 5(-2.45,0.6) 6(-2.45,0.2) 7(-2.45,-0.2) 8(-2.45,-0.6) 9(-2.45,-1) 10(-2.45,-1.4) 11(-2.45,-1.8) 12(-2.45,-2.2) 23(2.45,-2.2) 24(2.45,-1.8) 25(2.45,-1.4) 26(2.45,-1) 27(2.45,-0.6) 28(2.45,-0.2) 29(2.45,0.2) 30(2.45,0.6) 31(2.45,1) 32(2.45,1.4) 33(2.45,1.8) 34(2.45,2.2)
  rect 0.2x0.8 smd mask+0.05: 13(-1.8,-2.95) 14(-1.4,-2.95) 15(-1,-2.95) 16(-0.6,-2.95) 17(-0.2,-2.95) 18(0.2,-2.95) 19(0.6,-2.95) 20(1,-2.95) 21(1.4,-2.95) 22(1.8,-2.95) 35(1.8,2.95) 36(1.4,2.95) 37(1,2.95) 38(0.6,2.95) 39(0.2,2.95) 40(-0.2,2.95) 41(-0.6,2.95) 42(-1,2.95) 43(-1.4,2.95) 44(-1.8,2.95)
  rect 3.6x4.6 smd paste-1.8 mask+0.05: ep(0,0)
  silkscreen extent -2.5,-3 2.5,3, body extent -2.5,-3 2.5,3, height 0.81
IND_MURATA_DFE201612P [mm] "MCD-01491"
  rect 0.8x1.8 smd far side mask+0.05: 1(-0.8,0) 2(0.8,0)
  body extent -1.1,-0.9 1.1,0.9, height 1.2
L0603_H0P8 [mm]
  rect 0.8x0.95 smd mask+0.05: 1(-0.8,0) 2(0.8,0)
  silkscreen extent -1.33,-0.6 1.33,0.6, body extent -0.87,-0.47 0.87,0.47, height 0.9
R0402#1 [mm]
  rect 0.51x0.7 smd mask+0.05: 1(-0.45,0) 2(0.45,0)
  silkscreen extent -0.72,-0.43 0.72,0.43, body extent -0.52,-0.3 0.52,0.3, height 0.4
R0402#2 [mm]
  rect 0.51x0.7 smd far side mask+0.05: 1(-0.45,0) 2(0.45,0)
  body extent -0.52,-0.3 0.52,0.3, height 0.4
SWI_JIUBABA_C-TS-02H-2-5-B-V-T_R_BLUE [mm] "BLUE"
  rect 0.75x1 smd mask+0.05: 1(-2.225,0.75) 2(2.225,0.75) 3(-2.225,-0.75) 4(2.225,-0.75)
  silkscreen extent -1.85,-1.6 1.85,1.6, body extent -2.45,-1.6 2.45,1.6, height 2.6

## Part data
B1: library part MCD-00172, "Switch HW SMD blue", Manufacturer=JIUBABA, Manufacturer_Part_Number="C-TS-02H-2.5-B-V-T/R BLUE"
C1 C2 C3 C4 C5 C6 C7 C8 C9 C10 C11 C12 C17 C19 C20 C21 C22 C23 C24 C25 C26 C27 C28 C61 C64 C66 C71 C72 C73 C74 C78 C80 C82: library part MCD-00006, "Capacitor, MLCC, 100nF, 16V, X7R, 10%, 0402, T=0.5mm", Alternate_Manufacturer=MURATA, Alternate_Manufacturer_Part_Number=GCM155R71C104KA55D, Manufacturer=YAGEO, Manufacturer_Part_Number=CC0402KRX7R7BB104, Package=C0402
C13 C14 C30 C32 C35 C36 C37 C41 C45 C47 C48 C50 C53 C55 C56 C58 C59 C60 C65 C70 C75 C76 C77 C84 C85 C86 C87 C88 C89 C90 C91 C92 C93 C94 C95 C96 C97: library part MCD-00095, "Capacitor, MLCC, 1uF, 6V3, X5R, 10%, 0402, T=0,5mm", Alternate_Manufacturer=MURATA, Alternate_Manufacturer_Part_Number=GRM155R60J105KE19, Manufacturer_Part_Number=GRM155R61E105KA12, Package=C0402
C15 C16 C18 C31 C33 C39 C42 C46: library part MCD-00099, "Capacitor, MLCC, 10uF, 10V, X5R, 10%, 0603, T=0,8mm", Manufacturer=MURATA, Manufacturer_Part_Number=GRM188R61A106KE69D, Package=C0603
C29 C34 C38 C40 C62 C63: library part MCD-00100, "Capacitor, MLCC, 22uF, 6V3, X5R, 20%, 0603, T=0,8mm", Manufacturer=MURATA, Manufacturer_Part_Number=GRM188R60J226MEA0J, Package=C0603
C43 C49 C51 C52: library part MCD-01356, "Capacitor, MLCC, 4.7uF, 6V3, X5R, 20%, 0402, T=0,5mm", Manufacturer=MURATA, Manufacturer_Part_Number=GRM155R60J475ME47, Package=C0402
C44: library part MCD-00011, "Capacitor, MLCC, 10nF, 16V, X7R, 10%, 0402, T=0.5mm", Manufacturer=YAGEO, Manufacturer_Part_Number=CC0402KRX7R7BB103, Package=C0402
C54 C57: library part MCD-00198, "Capacitor, MLCC, 1nF, 16V, X7R, 10%, 0402, T=0.5mm", Manufacturer=YAGEO, Manufacturer_Part_Number=CC0402KRX7R7BB102, Package=C0402
C67 C68 C69: library part MCD-01823, "Capacitor,MLCC,2.2uF,6V3,X5R,10%,0402,T=0.5", Manufacturer=MURATA, Manufacturer_Part_Number=GRM155R60J225KE95D, Package=C0402
C79 C81 C83: library part MCD-00012, "Capacitor, MLCC, 2.2uF, 10V, X5R, 10%, 0603, T=0,8mm", Alternate_Manufacturer=KEMET, Alternate_Manufacturer_Part_Number=C0603C225K8PACTU, Manufacturer=YAGEO, Manufacturer_Part_Number=CC0603KRX5R6BB225, Package=C0603
L1 L2 L3 L4: library part MCD-01491, "Inductors 1.0uH 54mOhms3.3A +/-20% 2016", Manufacturer=MURATA, Manufacturer_Part_Number=DFE201612P-1R0M, Package=2016
L5: library part MCD-01134, "IND 4.7uH 20% 80mA 600mhom 0603", Manufacturer=MURATA, Manufacturer_Part_Number=LQM18FN4R7M00D, Package=0603
R1 R2 R3 R4 R5 R6 R7 R8 R9 R10 R11 R12 R13 R14 R15 R16 R17 R18 R19 R20 R21 R22 R23 R24 R25: library part MCD-00118, "Resistor,56R,0402,1%,1/16W", Manufacturer=YAGEO, Manufacturer_Part_Number=RC0402FR-0756RL, Package=R0402
R26 R27: library part MCD-00120, "Resistor,240R,0402,1%,1/16W", Manufacturer=YAGEO, Manufacturer_Part_Number=RC0402FR-07240RL, Package=R0402
R28: library part MCD-00119, "Resistor,100R,0402,1%,1/16W", Manufacturer=YAGEO, Manufacturer_Part_Number=RC0402FR-07100RL, Package=R0402
R29 R30 R40: library part MCD-00053, "Resistor,10K,0402,1%,1/16W", Manufacturer=YAGEO, Manufacturer_Part_Number=RC0402FR-0710KL, Package=R0402
R37 R38: library part MCD-00068, "Resistor,1K5,0402,1%,1/16W", Manufacturer=YAGEO, Manufacturer_Part_Number=RC0402FR-071K5L, Package=R0402
R39 R41 R42: library part MCD-00052, "Resistor,0R,0402,5%,1/16W", Manufacturer=YAGEO, Manufacturer_Part_Number=RC0402JR-070RL, Package=R0402
R43: library part MCD-00063, "Resistor,47K,0402,1%,1/16W", Manufacturer=YAGEO, Manufacturer_Part_Number=RC0402FR-0747KL, Package=R0402
U1: library part MCD-01805, "MPU LFBGA 16x16x1.271 PITCH 0.8 mm secure boot + crypto", Manufacturer=STMICROELECTRONICS, Package=LFBGA
U2: library part MCD-01811, "Memory,DDR3L,4Gb,256Mbx16,933Mhz,1V35,TFBGA", Manufacturer=NANYA, Manufacturer_Part_Number=NT5CC256M16ER-EK
U4: library part MCD-01650, "ST PMIC:  4 step-down + 1 advanced boost SMPS, 6 LDOs, 2 pwr switches, DDR Vref, NVM option 'A' for IO@3.3V", Manufacturer=STMICROELECTRONICS, Manufacturer_Part_Number=STPMIC1APQR, Package="WFQFN 5.0x6.0x0.80mm"
U5: library part MCD-00110, "Memory,e-MMC,4GB,3V3,WFBGA,153pins", Manufacturer=TOSHIBA, Manufacturer_Part_Number=THGBMDG5D1LBAIL

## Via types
v1: diameter 0.4, hole 0.2, Top Layer to Bottom Layer, tented both sides, 309 vias
v2: diameter 0.6, hole 0.3, Top Layer to Bottom Layer, tented both sides, 61 vias
v3: diameter 0.4, hole 0.2, Top Layer to Signal Layer 1, tented top, 2 vias

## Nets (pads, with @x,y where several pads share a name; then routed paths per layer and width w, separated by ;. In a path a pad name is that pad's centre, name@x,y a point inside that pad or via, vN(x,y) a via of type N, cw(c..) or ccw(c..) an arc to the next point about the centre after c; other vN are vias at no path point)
3V3: C32.2 C40.2 C78.2 C79.2 L4.2 U4.22 U4.27 U5.E6 U5.F5 U5.J10 U5.K9 | length 48.6
  Top Layer w0.175: U5.J10@27.15,88.475 U5.K9@27.65,88.975 v1(27.65,89.45) ; U5.E6@29.15,86.475 U5.F5@29.65,86.975 v1(30.075,86.975)
  Top Layer w0.2: 9.5,82.85 9.85,83.2 U4.22@10.05,83.2 ; v1(12.2,81.25) 12.2,81.85 12.4,82.05 U4.27@12.4,82.55
  Top Layer w0.3: C32.2@7.1,80.5 v1(7.1,80.85) 7.1,81.45 7.5,81.85 8.5,81.85 9.5,82.85
  Top Layer w0.5: C40.2@10.125,77.55 v1(10.8,77.55)
  Top Layer w0.6: C40.2@10.125,77.55 L4.2@10.125,78.75
  Signal Layer 2 w0.3: v1(7.1,80.85) 10.4,77.55 v1(10.8,77.55)
  Bottom Layer w0.1: C79.2@26.8,89.575 C79.2@26.925,89.45 ; v1@30,87.05 v1(30.075,86.975)
  Bottom Layer w0.3: v1(12.2,81.25) 11.525,80.575 11.525,77.75 11.325,77.55 v1(10.8,77.55) 10.8,81 11.925,82.125 15.05,82.125 15.625,81.55 19.525,81.55 21.7,83.725 22.075,83.725 23.625,85.275 23.625,86.4 C79.2@26.8,89.575 ; C79.2@26.925,89.45 v1(27.65,89.45) 28.1,89.45 C78.2@30,87.55 v1@30,87.05
5V_VIN: C18.2 C31.2 C33.2 C39.2 C41.2 C51.1 R43.2 U4.8 U4.12 U4.19 U4.24 U4.28 U4.36 U4.37 | length 15.1
  Top Layer w0.09: v1(12.8,81.15) U4.28@12.8,82.55
  Top Layer w0.12: R43.2@18.25,81.95 R43.2@18.3,82
  Top Layer w0.2: C39.2@9.3,80.45 9.525,80.675 9.525,80.875 10.1,81.45 10.6,81.45 11.2,82.05 U4.24@11.2,82.55 ; 9.35,84.4 U4.19@10.05,84.4 ; C31.2@12.4,80.45 12.8,80.85 v1(12.8,81.15) ; U4.8@12.4,87.45 12.4,88.85 v1(12.2,89.05) 12.2,89.55 C33.2@12.4,89.75 ; U4.36@15.95,83.6 16.625,83.6 v1(16.8,83.775) ; U4.37@15.95,84 16.575,84 v1(16.8,83.775) ; R43.2@18.3,82 C51.1@18.3,82.75 18.225,82.825 v1(17.75,82.825) v1(16.8,83.775)
  Top Layer w0.3: C41.2@7.65,83.95 v1(8.2,83.95) 8.65,84.4 9.35,84.4
  other v1: 9.1,81.05 9.5,87.85
DDR_A0: R1.1 U1.H18 U2.N3 | length 49.5
  Top Layer w0.12: U1.H18@38.4,64.3 v1(38.8,64.7) ; U2.N3@53.85,64 v1(54.25,64.4)
  Bottom Layer w0.12: v1(38.8,64.7) 39.24,64.7 39.32,64.78 39.32,64.97 39.48,65.13 39.74,65.13 39.96,65.35 39.96,65.749 39.7,66.009 39.7,66.452 39.245,66.907 39.245,67.266 39.7,67.721 39.7,69.358 40.04,69.698 40.04,70.01 39.7,70.35 39.7,70.976 43.799,75.075 44.195,75.075 44.275,74.995 44.725,74.995 44.805,75.075 45.22,75.075 45.3,74.995 45.95,74.995 46.03,75.075 46.575,75.075 46.65,75 47.025,75 47.1,75.075 47.604,75.075 47.834,74.845 48.17,74.845 48.4,75.075 48.63,75.075 48.825,74.88 48.825,71.225 48.55,70.95 48.55,65.35 49.98,63.92 53.11,63.92 53.22,63.81 53.91,63.81 54.25,64.15 v1(54.25,64.4) 54.25,64.65 54.69,65.09 54.69,65.349 54.901,65.56 55.079,65.56 55.569,66.05 56.8,66.05 56.96,65.89 57.48,65.89 57.63,65.74 65.14,65.74 65.21,65.67 R1.1@65.85,65.67
DDR_A1: R2.1 U1.M17 U2.P7 | length 45.4
  Top Layer w0.12: U1.M17@37.6,61.1 v1(38,60.7) ; U2.P7@53.05,60.8 v1(53.45,60.4)
  Bottom Layer w0.12: v1(38,60.7) 38.206,60.7 38.566,61.06 40.516,61.06 40.666,60.91 41.12,60.91 41.38,60.65 41.38,59.99 42.51,58.86 43.225,58.86 43.35,58.985 43.35,59.82 42.722,60.448 42.722,60.643 42.805,60.725 43.057,60.725 43.77,60.012 43.77,57.847 44.097,57.521 44.674,57.521 45.03,57.877 45.03,60.342 45.198,60.51 46.196,60.51 46.29,60.416 46.29,58.096 46.666,57.72 46.99,57.72 47.13,57.58 47.13,55.386 47.268,55.248 ; 47.27,55.25 47.446,55.25 47.546,55.35 47.546,60.346 47.7,60.5 49.1,60.5 49.4,60.8 53.05,60.8 v1(53.45,60.4) 53.741,60.4 54.101,60.04 54.98,60.04 55.06,59.96 55.55,59.96 55.94,59.57 57.41,59.57 57.57,59.41 58.23,59.41 58.551,59.089 58.77,59.089 59.05,58.809 59.05,58.29 60.05,57.29 60.27,57.29 60.73,56.83 R2.1@60.73,56.61
DDR_A2: R3.1 U1.G18 U2.P3 | length 42.7
  Top Layer w0.12: U1.G18@38.4,65.1 v1(38.8,65.5) ; U2.P3@53.05,64 v1(53.45,64.4)
  Bottom Layer w0.12: v1@38.82,65.5 38.82,66.144 38.46,66.504 38.46,67.669 38.86,68.069 38.86,71.324 43.736,76.2 43.95,76.2 44.235,75.915 44.44,75.915 44.725,76.2 44.925,76.2 45.21,75.915 45.415,75.915 45.7,76.2 45.875,76.2 46.16,75.915 46.35,75.915 46.635,76.2 46.842,76.2 47.128,75.915 47.35,75.915 47.635,76.2 47.86,76.2 48.145,75.915 48.365,75.915 48.575,76.125 48.768,76.125 49.575,75.318 49.575,70.9 49.175,70.5 49.175,65.523 50.298,64.4 52.33,64.4 52.373,64.443 v1@53.43,64.443 ; v1(53.45,64.4) 53.45,64.65 53.83,65.03 53.83,65.51 54.29,65.97 54.29,66.34 57.08,69.13 R3.1@57.08,69.45
DDR_A3: R4.1 U1.F19 U2.N2 | length 42
  Top Layer w0.12: U1.F19@39.2,65.9 v1(39.6,65.5) ; U2.N2@53.85,64.8 v1(54.25,65.2)
  Bottom Layer w0.12: v1(39.6,65.5) 39.275,65.5 39.2,65.575 39.2,66.358 38.825,66.733 38.825,67.44 39.28,67.895 39.28,71.15 43.625,75.495 48.804,75.495 49.225,75.074 49.225,71.125 48.85,70.75 48.85,65.45 50.14,64.16 53.181,64.16 53.301,64.04 53.74,64.04 53.84,64.14 53.84,64.701 54.25,65.111 v1(54.25,65.2) 54.25,65.51 54.5,65.76 54.799,65.76 58.11,69.071 R4.1@58.11,69.45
